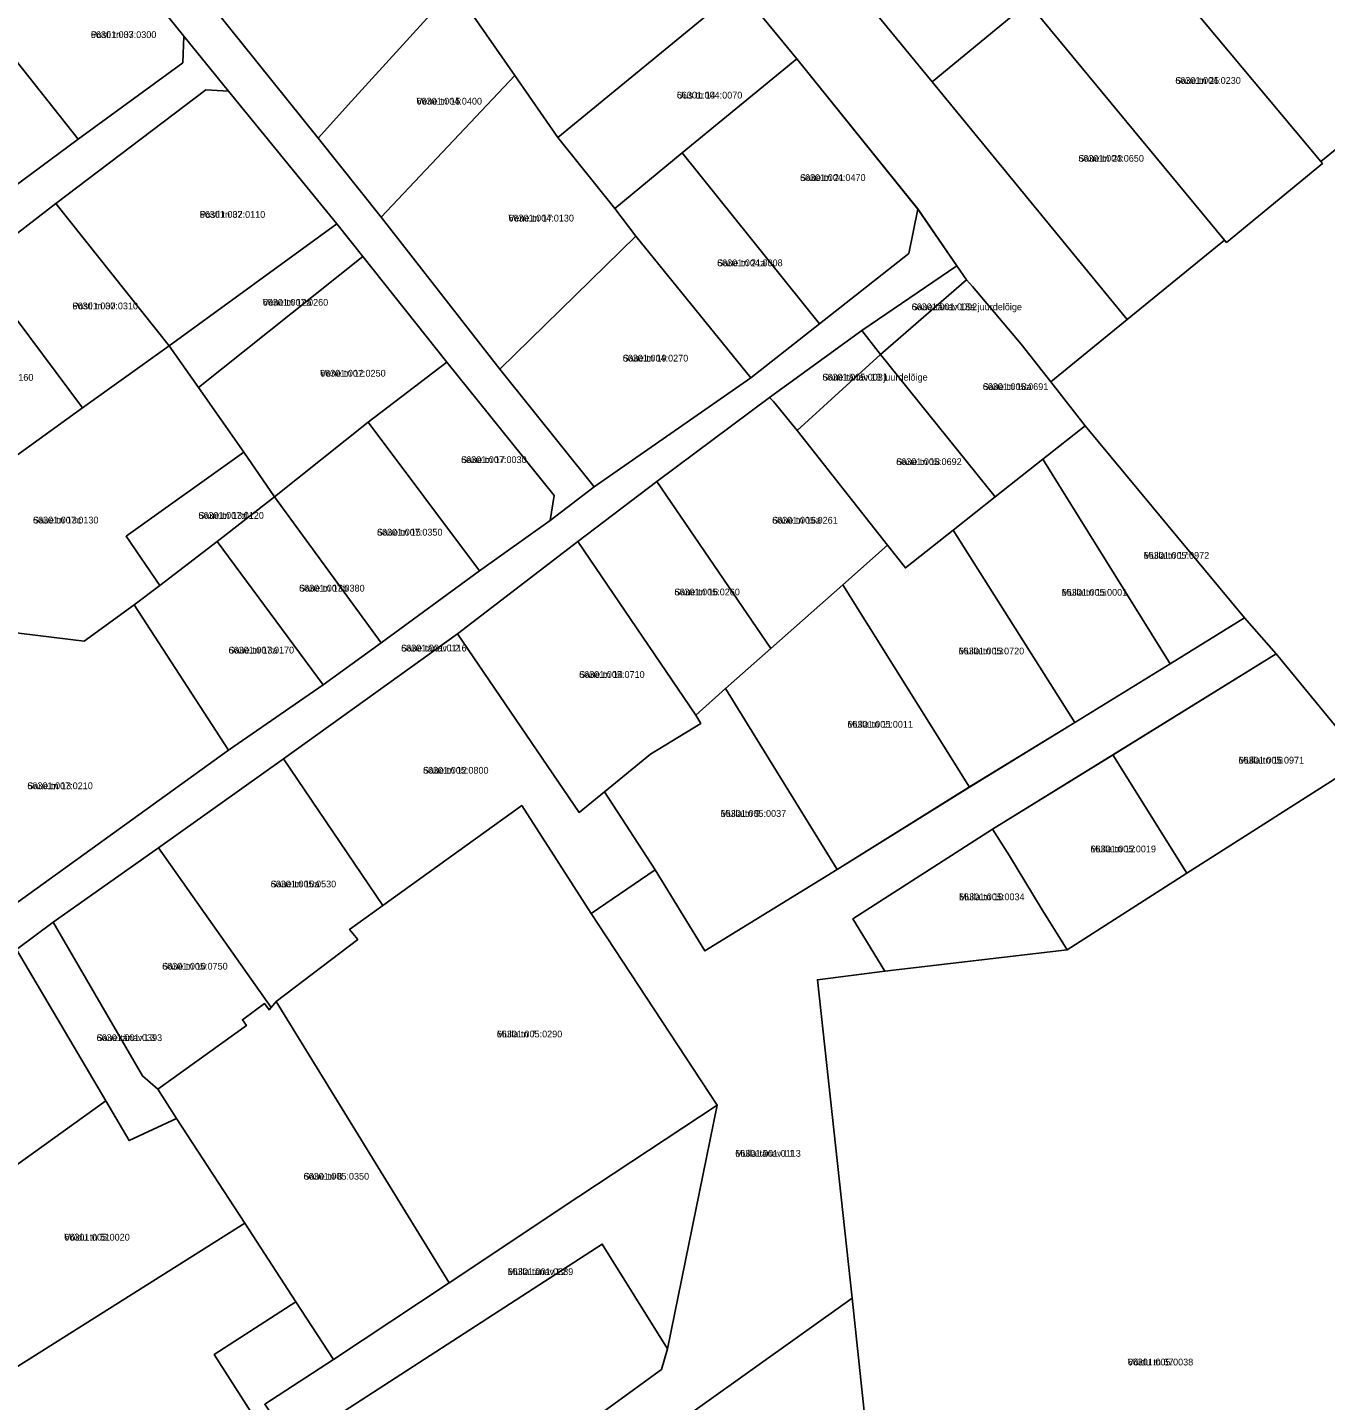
# Model space of a CAD drawing. Extents: x 632278 to 636344, y 6578401 to 6583362.
# Drawn here: x 634584.8 to 634872.1, y 6581420.2 to 6581724.1 of the extents above; entities that cross this region are included whole.
import ezdxf

# ---------------------------------------------------------------- set-up
doc = ezdxf.new("R2010")
doc.units = 0
for name, color, linetype in [('L_AADRESS', 7, 'Continuous'), ('PIIR', 7, 'Continuous'), ('TUNNUS', 7, 'Continuous')]:
    doc.layers.add(name, color=color, linetype=linetype)

msp = doc.modelspace()

# ---------------------------------------------------------------- linework, layer by layer
at = {"layer": 'PIIR'}
for points in [[(634542.38, 6581659.66), (634528.25, 6581681.09), (634505.64, 6581667.69), (634501.78, 6581673.52), (634499.19, 6581671.71), (634476.56, 6581704.76), (634470.29, 6581713.85), (634463.54, 6581723.76), (634462.17, 6581725.81), (634478.91, 6581739.1), (634495.28, 6581752.06), (634495.31, 6581755.28), (634480.74, 6581776.54), (634487.79, 6581781.63), (634501.69, 6581761.6), (634506.42, 6581760.84), (634533.2, 6581780.82), (634535.35, 6581782.3), (634539.41, 6581777.64), (634559.86, 6581753.58), (634578.17, 6581731.87), (634573.15, 6581728.47), (634575.51, 6581725.17), (634596.02, 6581699.37)], [(634785.04, 6581712), (634749.69, 6581755.05), (634770.93, 6581772.51), (634806.28, 6581729.53)], [(634650.36, 6581763.08), (634665.49, 6581744.26), (634677.02, 6581730.35), (634656.47, 6581707.77), (634649.14, 6581699.55), (634621.98, 6581733.45)], [(634848.44, 6581764.18), (634891.71, 6581711.25), (634871.06, 6581694.38), (634827.18, 6581746.96)], [(634719.07, 6581760.66), (634742.28, 6581732.68), (634702.14, 6581699.71), (634692.62, 6581713.41), (634681.83, 6581728.97)], [(634827.18, 6581746.96), (634871.06, 6581694.38), (634871.4, 6581693.99), (634850.19, 6581676.48), (634849.75, 6581677.02), (634806.28, 6581729.53)], [(634575.51, 6581725.17), (634601.75, 6581744.08), (634619.36, 6581722.13), (634619.15, 6581716.25), (634596.02, 6581699.37)], [(634649.14, 6581699.55), (634656.47, 6581707.77), (634677.02, 6581730.35), (634679.26, 6581732.06), (634681.83, 6581728.97), (634692.62, 6581713.41), (634663.03, 6581682.08)], [(634702.14, 6581699.71), (634742.28, 6581732.68), (634755.08, 6581717.15), (634729.7, 6581696.29), (634714.75, 6581684)], [(634806.28, 6581729.53), (634849.75, 6581677.02), (634828.19, 6581659.44), (634785.04, 6581712)], [(634465.25, 6581603.88), (634468.13, 6581604.4), (634488.84, 6581619.91), (634496.87, 6581625.93), (634517.35, 6581641.08), (634542.38, 6581659.66), (634596.02, 6581699.37), (634619.15, 6581716.25), (634619.36, 6581722.13), (634629.3, 6581709.96), (634624.28, 6581710.25), (634591.07, 6581685.14), (634573.32, 6581671.48), (634546.18, 6581651.15), (634521.83, 6581632.88), (634504.86, 6581620.14), (634492.15, 6581611.16), (634470.5, 6581595.28)], [(634755.08, 6581717.15), (634781.85, 6581683.89), (634779.88, 6581674.06), (634760.1, 6581658.51), (634729.7, 6581696.29)], [(634663.03, 6581682.08), (634692.62, 6581713.41), (634702.14, 6581699.71), (634714.75, 6581684), (634719.44, 6581677.87), (634689.34, 6581648.45)], [(634629.3, 6581709.96), (634653.25, 6581680.62), (634616.16, 6581653.62), (634591.07, 6581685.14), (634624.28, 6581710.25)], [(634714.75, 6581684), (634729.7, 6581696.29), (634760.1, 6581658.51), (634744.9, 6581646.56), (634719.44, 6581677.87)], [(634591.07, 6581685.14), (634616.16, 6581653.62), (634596.98, 6581639.85), (634573.32, 6581671.48)], [(634616.16, 6581653.62), (634653.25, 6581680.62), (634658.99, 6581673.41), (634622.65, 6581644.36)], [(634689.34, 6581648.45), (634719.44, 6581677.87), (634744.9, 6581646.56), (634710.22, 6581622.39)], [(634632.64, 6581630.11), (634622.65, 6581644.36), (634658.99, 6581673.41), (634677.61, 6581649.98), (634660.18, 6581636.74), (634639.45, 6581620.18)], [(634558.68, 6581636.62), (634550.9, 6581644.45), (634546.18, 6581651.15), (634573.32, 6581671.48), (634596.98, 6581639.85), (634570.79, 6581621.02)], [(634769.45, 6581656.97), (634790.51, 6581671.31), (634792.63, 6581668.24), (634773.6, 6581651.67)], [(634798.99, 6581620.19), (634773.6, 6581651.67), (634792.65, 6581668.24), (634793.94, 6581666.77), (634804.7, 6581653.95), (634811.29, 6581645.66), (634818.86, 6581635.92), (634809.5, 6581628.5)], [(634769.45, 6581656.97), (634773.6, 6581651.67), (634755.13, 6581634.88), (634749.92, 6581641.32), (634749.01, 6581642.2)], [(634559.13, 6581574.95), (634542.92, 6581601.03), (634570.79, 6581621.02), (634596.98, 6581639.85), (634616.16, 6581653.62), (634622.65, 6581644.36), (634632.64, 6581630.11), (634606.62, 6581611.45), (634614.1, 6581600.53), (634608.38, 6581596.32), (634597.33, 6581588.27), (634579.85, 6581590.37)], [(634701.34, 6581620.5), (634700.48, 6581614.98), (634684.83, 6581603.81), (634660.18, 6581636.74), (634677.61, 6581649.98)], [(634775.16, 6581609.48), (634755.13, 6581634.88), (634773.6, 6581651.67), (634798.99, 6581620.19), (634789.68, 6581612.8), (634779.12, 6581604.44)], [(634724.09, 6581623.61), (634749.01, 6581642.2), (634749.92, 6581641.32), (634755.13, 6581634.88), (634775.16, 6581609.48), (634765.22, 6581600.71), (634749.31, 6581586.64)], [(634660.18, 6581636.74), (634684.83, 6581603.81), (634663.05, 6581587.86), (634639.45, 6581620.18)], [(634818.86, 6581635.92), (634854.19, 6581593.39), (634837.7, 6581583.25), (634809.5, 6581628.5)], [(634639.45, 6581620.18), (634626.75, 6581610.33), (634614.1, 6581600.53), (634606.62, 6581611.45), (634632.64, 6581630.11)], [(634789.68, 6581612.8), (634798.99, 6581620.19), (634809.5, 6581628.5), (634837.7, 6581583.25), (634816.57, 6581570.27)], [(634724.09, 6581623.61), (634749.31, 6581586.64), (634739.26, 6581577.8), (634732.68, 6581571.87), (634706.61, 6581610.27)], [(634639.45, 6581620.18), (634663.05, 6581587.86), (634650.19, 6581578.56), (634626.75, 6581610.33)], [(634765.22, 6581600.71), (634775.16, 6581609.48), (634779.12, 6581604.44), (634789.68, 6581612.8), (634816.57, 6581570.27), (634793.28, 6581555.95)], [(634608.38, 6581596.32), (634614.1, 6581600.53), (634626.75, 6581610.33), (634650.19, 6581578.56), (634629.28, 6581564.12)], [(634679.95, 6581589.86), (634706.61, 6581610.27), (634732.68, 6581571.87), (634733.81, 6581570.05), (634722.66, 6581563.21), (634712.47, 6581554.9), (634706.88, 6581550.36)], [(634765.22, 6581600.71), (634793.28, 6581555.95), (634763.96, 6581537.72), (634739.26, 6581577.8), (634749.31, 6581586.64)], [(634538.81, 6581546.18), (634565.3, 6581564.63), (634559.13, 6581574.95), (634579.85, 6581590.37), (634597.33, 6581588.27), (634608.38, 6581596.32), (634629.28, 6581564.12), (634560.66, 6581514.66), (634555.66, 6581521.89)], [(634641.41, 6581562.19), (634679.95, 6581589.86), (634706.88, 6581550.36), (634712.47, 6581554.9), (634723.69, 6581537.61), (634709.57, 6581527.99), (634694.19, 6581551.85), (634663.45, 6581529.74)], [(634825.04, 6581563.1), (634861.16, 6581585.42), (634880.57, 6581561.87), (634841.41, 6581536.87)], [(634739.26, 6581577.8), (634763.96, 6581537.72), (634734.71, 6581519.71), (634723.69, 6581537.61), (634712.47, 6581554.9), (634722.66, 6581563.21), (634733.81, 6581570.05), (634732.68, 6581571.87)], [(634638.71, 6581507.16), (634613.77, 6581542.5), (634641.41, 6581562.19), (634663.45, 6581529.74), (634656.09, 6581524.44), (634657.88, 6581522.24), (634639.84, 6581508.52)], [(634825.04, 6581563.1), (634841.41, 6581536.87), (634814.93, 6581519.91), (634809.13, 6581529.18), (634802.12, 6581540.7), (634798.38, 6581546.61)], [(634706.81, 6581465.37), (634678.14, 6581446.22), (634639.84, 6581508.52), (634657.88, 6581522.24), (634656.09, 6581524.44), (634663.45, 6581529.74), (634694.19, 6581551.85), (634709.57, 6581527.99), (634737.46, 6581485.56)], [(634798.38, 6581546.61), (634802.12, 6581540.7), (634809.13, 6581529.18), (634814.93, 6581519.91), (634774.57, 6581515.21), (634767.45, 6581526.78)], [(634610.22, 6581492.03), (634590.48, 6581526.02), (634613.77, 6581542.5), (634638.71, 6581507.16), (634638.26, 6581506.64), (634637.27, 6581508.04), (634632.34, 6581504.46), (634633.25, 6581503.15), (634613.64, 6581489.09)], [(634590.48, 6581526.02), (634610.22, 6581492.03), (634613.64, 6581489.09), (634617.77, 6581482.58), (634607.27, 6581477.71), (634602.13, 6581486.49), (634582.38, 6581520.02)], [(634537.33, 6581488.04), (634582.38, 6581520.02), (634602.13, 6581486.49), (634558.25, 6581454.99)], [(634632.85, 6581459.43), (634617.77, 6581482.58), (634613.64, 6581489.09), (634633.25, 6581503.15), (634632.34, 6581504.46), (634637.27, 6581508.04), (634638.26, 6581506.64), (634638.71, 6581507.16), (634639.84, 6581508.52), (634678.14, 6581446.22), (634652.51, 6581429.29), (634644.18, 6581442.06)], [(634602.13, 6581486.49), (634607.27, 6581477.71), (634617.77, 6581482.58), (634632.85, 6581459.43), (634577.69, 6581424.67), (634558.25, 6581454.99)], [(634637.29, 6581419.37), (634652.51, 6581429.29), (634678.14, 6581446.22), (634706.81, 6581465.37), (634737.46, 6581485.56), (634726.44, 6581431.65), (634711.98, 6581454.81), (634643.37, 6581410.37)], [(634632.85, 6581459.43), (634644.18, 6581442.06), (634626.13, 6581430.34), (634634.36, 6581417.47), (634626.35, 6581412.01), (634651.31, 6581373.42), (634627.04, 6581356.26), (634621.73, 6581353.95), (634577.69, 6581424.67)], [(634626.35, 6581412.01), (634634.36, 6581417.47), (634626.13, 6581430.34), (634644.18, 6581442.06), (634652.51, 6581429.29), (634637.29, 6581419.37), (634643.37, 6581410.37), (634711.98, 6581454.81), (634726.44, 6581431.65), (634725.11, 6581427.06), (634651.31, 6581373.42)], [(634767.34, 6581442.85), (634772.59, 6581393.46), (634775.6, 6581389.02), (634777.69, 6581365.33), (634751.77, 6581346.77), (634738.02, 6581365.95), (634729.95, 6581377.35), (634711.44, 6581403.03)]]:
    msp.add_lwpolyline(points, close=True, dxfattribs=at)
for points in [[(634749.69, 6581755.05), (634785.04, 6581712.01), (634828.19, 6581659.45), (634811.29, 6581645.67), (634804.7, 6581653.95), (634793.94, 6581666.77), (634792.65, 6581668.24), (634790.51, 6581671.31), (634781.85, 6581683.9), (634755.08, 6581717.15), (634742.28, 6581732.68)], [(634621.98, 6581733.46), (634649.14, 6581699.56), (634663.03, 6581682.08), (634689.34, 6581648.46), (634710.22, 6581622.4), (634700.48, 6581614.98), (634701.33, 6581620.51), (634677.61, 6581649.98), (634658.98, 6581673.41), (634653.24, 6581680.62), (634629.3, 6581709.97), (634619.36, 6581722.14), (634601.75, 6581744.09)], [(635010.04, 6581726.18), (635004.04, 6581679.37), (635014.06, 6581648.05), (635016.56, 6581622.38), (635016.6, 6581620.48), (635013.75, 6581602.14), (635000.2, 6581574.59), (634957.44, 6581478.78), (634960.77, 6581506.3), (634960.01, 6581539.73), (634959.06, 6581572.85), (634904.19, 6581570.97), (634880.57, 6581561.87), (634861.16, 6581585.42), (634854.19, 6581593.39), (634818.86, 6581635.92), (634811.29, 6581645.66), (634828.19, 6581659.44), (634849.75, 6581677.02), (634850.19, 6581676.48), (634871.4, 6581693.99), (634871.06, 6581694.38), (634891.71, 6581711.25), (634913.86, 6581729.07)], [(634560.66, 6581514.66), (634629.28, 6581564.12), (634650.19, 6581578.56), (634663.05, 6581587.86), (634684.83, 6581603.81), (634700.48, 6581614.98), (634710.22, 6581622.39), (634744.9, 6581646.56), (634760.1, 6581658.51), (634779.88, 6581674.06), (634781.85, 6581683.89), (634790.51, 6581671.31), (634769.45, 6581656.97), (634749.01, 6581642.2), (634724.09, 6581623.61), (634706.61, 6581610.27), (634679.95, 6581589.86), (634641.41, 6581562.19), (634613.77, 6581542.5), (634590.48, 6581526.02), (634582.38, 6581520.02)], [(634651.31, 6581373.43), (634725.1, 6581427.07), (634726.44, 6581431.65), (634737.46, 6581485.56), (634709.57, 6581527.99), (634723.68, 6581537.62), (634734.71, 6581519.71), (634763.96, 6581537.72), (634793.28, 6581555.97), (634816.57, 6581570.28), (634837.7, 6581583.26), (634854.19, 6581593.4), (634861.16, 6581585.42), (634825.07, 6581563.1), (634798.38, 6581546.61), (634767.45, 6581526.78), (634774.57, 6581515.21), (634759.62, 6581513.31), (634767.34, 6581442.86), (634711.44, 6581403.03)], [(634757.02, 6581255.3), (634760.32, 6581263.95), (634752.99, 6581266.7), (634753.73, 6581268.73), (634767.88, 6581273.86), (634791.94, 6581276.36), (634798.32, 6581287.05), (634798.08, 6581319.59), (634795.84, 6581322.71), (634788.66, 6581333.04), (634782.11, 6581347.23), (634777.69, 6581365.33), (634775.6, 6581389.02), (634772.59, 6581393.46), (634767.34, 6581442.85), (634759.62, 6581513.31), (634774.57, 6581515.21), (634814.93, 6581519.91), (634841.41, 6581536.87), (634880.57, 6581561.87)]]:
    msp.add_lwpolyline(points, dxfattribs=at)

# ---------------------------------------------------------------- texts
at = {"layer": 'L_AADRESS'}
for s, p in [('Posti tn 33', (634598.8, 6581721.73)), ('Saue tn 25', (634838.84, 6581711.59)), ('Uus tn 14', (634728.5, 6581708.34)), ('Vene tn 15', (634670.88, 6581707)), ('Saue tn 23', (634817.39, 6581694.35)), ('Saue tn 21', (634755.78, 6581690.09)), ('Posti tn 32', (634622.9, 6581681.94)), ('Vene tn 17', (634691.23, 6581681.12)), ('Saue tn 21a', (634737.43, 6581671.22)), ('Posti tn 30', (634594.74, 6581661.69)), ('Vene tn 12a', (634636.84, 6581662.49)), ('Saue tänav 18a juurdelõige', (634780.48, 6581661.49)), ('Saue tn 19', (634716.53, 6581650.13)), ('Vene tn 12', (634649.56, 6581646.79)), ('Saue tänav 18 juurdelõige', (634760.72, 6581645.92)), ('Saue tn 18a', (634796.23, 6581643.83)), ('Saue tn 17', (634680.76, 6581627.66)), ('Saue tn 18', (634777.06, 6581627.22)), ('Saue tn 13c', (634585.99, 6581614.29)), ('Saue tn 13d', (634622.6, 6581615.32)), ('Saue tn 16a', (634749.62, 6581614.26)), ('Saue tn 15', (634662.14, 6581611.61)), ('Mulla tn 17', (634831.84, 6581606.47)), ('Saue tn 13b', (634644.9, 6581599.22)), ('Saue tn 16', (634727.96, 6581598.38)), ('Mulla tn 15', (634813.69, 6581598.3)), ('Saue tn 13a', (634629.29, 6581585.51)), ('Saue tänav L2', (634667.48, 6581585.96)), ('Mulla tn 13', (634790.89, 6581585.32)), ('Saue tn 14', (634706.88, 6581580.12)), ('Mulla tn 11', (634766.27, 6581569.1)), ('Mulla tn 16', (634852.85, 6581561.15)), ('Saue tn 12', (634672.33, 6581558.92)), ('Saue tn 13', (634584.74, 6581555.49)), ('Mulla tn 9', (634738.21, 6581549.36)), ('Mulla tn 12', (634820.06, 6581541.51)), ('Saue tn 10a', (634638.61, 6581533.75)), ('Mulla tn 10', (634790.98, 6581530.91)), ('Saue tn 10', (634614.59, 6581515.55)), ('Saue tänav L3', (634600.08, 6581499.74)), ('Mulla tn 7', (634688.65, 6581500.55)), ('Mulla tänav L1', (634741.44, 6581474.13)), ('Saue tn 8', (634645.89, 6581469.06)), ('Võidu tn 51', (634592.91, 6581455.58)), ('Mulla tänav L2', (634691.08, 6581447.96)), ('Võidu tn 67', (634828.3, 6581427.95))]:
    msp.add_text(s, height=1.5, dxfattribs=at).set_placement(p)
at = {"layer": 'TUNNUS'}
for s, p in [('66301:007:0300', (634598.8, 6581721.73)), ('66301:004:0230', (634838.84, 6581711.59)), ('66301:004:0070', (634728.5, 6581708.34)), ('66301:004:0400', (634670.88, 6581707)), ('66301:004:0650', (634817.39, 6581694.35)), ('66301:004:0470', (634755.78, 6581690.09)), ('66301:007:0110', (634622.9, 6581681.94)), ('66301:004:0130', (634691.23, 6581681.12)), ('66301:004:0008', (634737.43, 6581671.22)), ('66301:007:0310', (634594.74, 6581661.69)), ('66301:007:0260', (634636.84, 6581662.49)), ('66301:001:0092', (634780.48, 6581661.49)), ('66301:004:0270', (634716.53, 6581650.13)), ('66301:007:0160', (634571.58, 6581645.88)), ('66301:007:0250', (634649.56, 6581646.79)), ('66301:005:0031', (634760.72, 6581645.92)), ('66301:005:0691', (634796.23, 6581643.83)), ('66301:007:0030', (634680.76, 6581627.66)), ('66301:005:0692', (634777.06, 6581627.22)), ('66301:007:0130', (634585.99, 6581614.29)), ('66301:007:0120', (634622.6, 6581615.32)), ('66301:005:0261', (634749.62, 6581614.26)), ('66301:007:0350', (634662.14, 6581611.61)), ('66301:005:0972', (634831.84, 6581606.47)), ('66301:007:0380', (634644.9, 6581599.22)), ('66301:005:0260', (634727.96, 6581598.38)), ('66301:005:0001', (634813.69, 6581598.3)), ('66301:007:0170', (634629.29, 6581585.51)), ('66301:001:0116', (634667.48, 6581585.96)), ('66301:005:0720', (634790.89, 6581585.32)), ('66301:005:0710', (634706.88, 6581580.12)), ('66301:005:0011', (634766.27, 6581569.1)), ('66301:005:0971', (634852.85, 6581561.15)), ('66301:005:0800', (634672.33, 6581558.92)), ('66301:007:0210', (634584.74, 6581555.49)), ('66301:005:0037', (634738.21, 6581549.36)), ('66301:005:0019', (634820.06, 6581541.51)), ('66301:005:0530', (634638.61, 6581533.75)), ('66301:005:0034', (634790.98, 6581530.91)), ('66301:005:0750', (634614.59, 6581515.55)), ('66301:001:0393', (634600.08, 6581499.74)), ('66301:005:0290', (634688.65, 6581500.55)), ('66301:001:0113', (634741.44, 6581474.13)), ('66301:005:0350', (634645.89, 6581469.06)), ('66301:005:0020', (634592.91, 6581455.58)), ('66301:001:0389', (634691.08, 6581447.96)), ('66301:005:0038', (634828.3, 6581427.95))]:
    msp.add_text(s, height=1.5, dxfattribs=at).set_placement(p)

doc.saveas('drawing.dxf')
